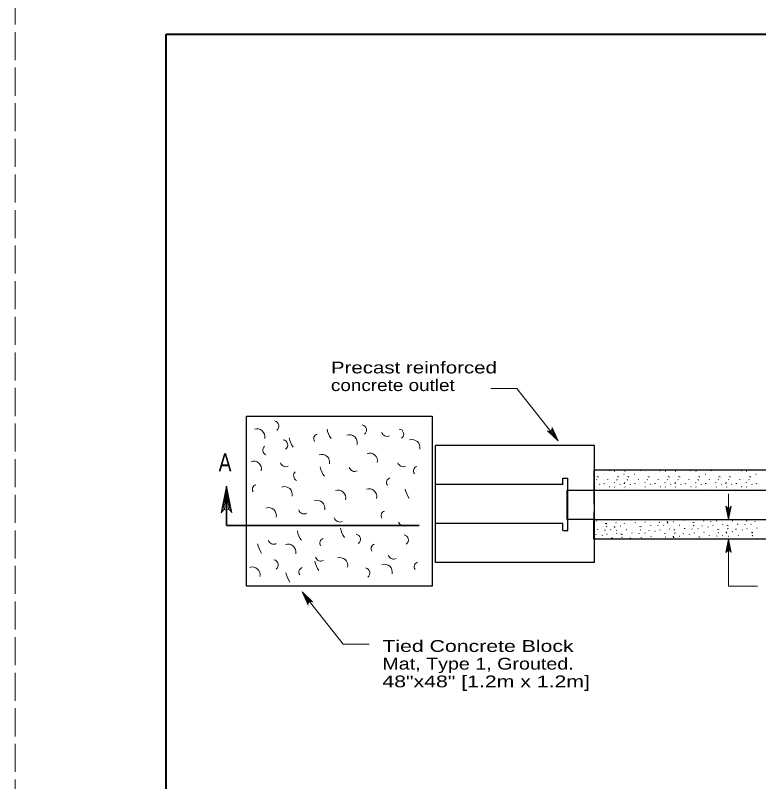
# Model space of a CAD drawing. Extents: x 1083.1 to 1117.1, y 697.4 to 741.4.
# Drawn here: x 1083.13 to 1092.98, y 708.94 to 719.1 of the extents above; entities that cross this region are included whole.
import ezdxf

# ---------------------------------------------------------------- set-up
doc = ezdxf.new("R2010")
doc.units = 0
doc.header["$LTSCALE"] = 0.062
doc.linetypes.add('LONG_DASHED', pattern=[7.5, 6, -1.5])
doc.linetypes.add('MEDIUM_DASHED', pattern=[4.5, 3, -1.5])
doc.layers.add('1', color=7, linetype='Continuous', lineweight=13)

msp = doc.modelspace()

# ---------------------------------------------------------------- linework, layer by layer
at = {"layer": '1', "lineweight": 25}
for p, q in [((1085.12642, 718.85408), (1116.62642, 718.85408)), ((1088.69717, 711.84625), (1088.69717, 713.39942)), ((1090.80558, 713.39942), (1088.69717, 713.39942)), ((1090.80558, 711.84625), (1090.80558, 713.39992)), ((1090.80308, 713.06008), (1090.80533, 713.05683)), ((1091.00475, 713.06617), (1091.007, 713.06283)), ((1091.07075, 713.06008), (1091.07308, 713.05683)), ((1091.20833, 713.06008), (1091.21058, 713.05683)), ((1091.41, 713.06617), (1091.41217, 713.06283)), ((1091.476, 713.06008), (1091.47825, 713.05683)), ((1091.67767, 713.06617), (1091.67992, 713.06283)), ((1091.74367, 713.06008), (1091.746, 713.05683)), ((1091.88117, 713.06008), (1091.8835, 713.05683)), ((1092.08292, 713.06617), (1092.08508, 713.06283)), ((1092.14892, 713.06008), (1092.15117, 713.05683)), ((1092.35058, 713.06617), (1092.35283, 713.06283)), ((1092.41658, 713.06008), (1092.41892, 713.05683)), ((1092.55408, 713.06008), (1092.55642, 713.05683)), ((1092.75583, 713.06617), (1092.758, 713.06283)), ((1092.82183, 713.06008), (1092.82408, 713.05683)), ((1090.45158, 712.27133), (1090.45158, 712.96725)), ((1090.83267, 712.947), (1090.83483, 712.94358)), ((1090.83483, 712.94575), (1090.83708, 712.94233)), ((1090.84442, 712.98292), (1090.84658, 712.988)), ((1090.8525, 712.98292), (1090.85475, 712.97967)), ((1090.92742, 713.0205), (1090.92975, 713.01708)), ((1090.98017, 712.947), (1090.98242, 712.952)), ((1091.10033, 712.947), (1091.10258, 712.94358)), ((1091.10258, 712.94575), (1091.10475, 712.94233)), ((1091.11208, 712.98292), (1091.11425, 712.988)), ((1091.12017, 712.98292), (1091.1225, 712.97967)), ((1091.19517, 713.0205), (1091.19742, 713.01708)), ((1091.23783, 712.947), (1091.24008, 712.94358)), ((1091.24008, 712.94575), (1091.24225, 712.94233)), ((1091.24958, 712.98292), (1091.25175, 712.988)), ((1091.25767, 712.98292), (1091.26, 712.97967)), ((1091.33267, 713.0205), (1091.33492, 713.01708)), ((1091.38533, 712.947), (1091.38767, 712.952)), ((1091.50558, 712.947), (1091.50775, 712.94358)), ((1091.50775, 712.94575), (1091.51, 712.94233)), ((1091.51725, 712.98292), (1091.5195, 712.988)), ((1091.52542, 712.98292), (1091.52767, 712.97967)), ((1091.60033, 713.0205), (1091.60267, 713.01708)), ((1091.65308, 712.947), (1091.65533, 712.952)), ((1091.77325, 712.947), (1091.7755, 712.94358)), ((1091.7755, 712.94575), (1091.77767, 712.94233)), ((1091.785, 712.98292), (1091.78717, 712.988)), ((1091.79308, 712.98292), (1091.79533, 712.97967)), ((1091.86808, 713.0205), (1091.87033, 713.01708)), ((1091.91075, 712.947), (1091.913, 712.94358)), ((1091.913, 712.94575), (1091.91517, 712.94233)), ((1091.9225, 712.98292), (1091.92475, 712.988)), ((1091.93058, 712.98292), (1091.93292, 712.97967)), ((1092.00558, 713.0205), (1092.00783, 713.01708)), ((1092.05825, 712.947), (1092.06058, 712.952)), ((1092.1785, 712.947), (1092.18067, 712.94358)), ((1092.18067, 712.94575), (1092.18292, 712.94233)), ((1092.19025, 712.98292), (1092.19242, 712.988)), ((1092.19833, 712.98292), (1092.20058, 712.97967)), ((1092.27325, 713.0205), (1092.27558, 713.01708)), ((1092.326, 712.947), (1092.32825, 712.952)), ((1092.44617, 712.947), (1092.44842, 712.94358)), ((1092.44842, 712.94575), (1092.45058, 712.94233)), ((1092.45792, 712.98292), (1092.46008, 712.988)), ((1092.466, 712.98292), (1092.46833, 712.97967)), ((1092.541, 713.0205), (1092.54325, 713.01708)), ((1092.58367, 712.947), (1092.58592, 712.94358)), ((1092.58592, 712.94575), (1092.58808, 712.94233)), ((1092.59542, 712.98292), (1092.59758, 712.988)), ((1092.6035, 712.98292), (1092.60583, 712.97967)), ((1092.6785, 713.0205), (1092.68075, 713.01708)), ((1092.73117, 712.947), (1092.7335, 712.952)), ((1092.85142, 712.947), (1092.85358, 712.94358)), ((1092.85358, 712.94575), (1092.85583, 712.94233)), ((1092.86308, 712.98292), (1092.86533, 712.988)), ((1092.87125, 712.98292), (1092.8735, 712.97967)), ((1092.94617, 713.0205), (1092.9485, 713.01708)), ((1090.38533, 712.88175), (1088.69717, 712.88175)), ((1090.79958, 712.9055), (1090.80192, 712.91058)), ((1090.80308, 712.85083), (1090.80533, 712.84758)), ((1090.87242, 712.88617), (1090.87458, 712.88283)), ((1090.93492, 712.89267), (1090.93708, 712.89775)), ((1091.00475, 712.85692), (1091.007, 712.85358)), ((1091.06733, 712.9055), (1091.06958, 712.91058)), ((1091.07075, 712.85083), (1091.07308, 712.84758)), ((1091.14008, 712.88617), (1091.14225, 712.88283)), ((1091.20258, 712.89267), (1091.20483, 712.89775)), ((1091.20483, 712.9055), (1091.20708, 712.91058)), ((1091.20833, 712.85083), (1091.21058, 712.84758)), ((1091.27758, 712.88617), (1091.27983, 712.88283)), ((1091.34017, 712.89267), (1091.34233, 712.89775)), ((1091.41, 712.85692), (1091.41217, 712.85358)), ((1091.4725, 712.9055), (1091.47483, 712.91058)), ((1091.476, 712.85083), (1091.47825, 712.84758)), ((1091.54533, 712.88617), (1091.5475, 712.88283)), ((1091.60783, 712.89267), (1091.61008, 712.89775)), ((1091.67767, 712.85692), (1091.67992, 712.85358)), ((1091.74025, 712.9055), (1091.7425, 712.91058)), ((1091.74367, 712.85083), (1091.746, 712.84758)), ((1091.813, 712.88617), (1091.81517, 712.88283)), ((1091.87558, 712.89267), (1091.87775, 712.89775)), ((1091.87775, 712.9055), (1091.88, 712.91058)), ((1091.88117, 712.85083), (1091.8835, 712.84758)), ((1091.9505, 712.88617), (1091.95267, 712.88283)), ((1092.01308, 712.89267), (1092.01525, 712.89775)), ((1092.08292, 712.85692), (1092.08508, 712.85358)), ((1092.14542, 712.9055), (1092.14775, 712.91058)), ((1092.14892, 712.85083), (1092.15117, 712.84758)), ((1092.21817, 712.88617), (1092.22042, 712.88283)), ((1092.28075, 712.89267), (1092.28292, 712.89775)), ((1092.35058, 712.85692), (1092.35283, 712.85358)), ((1092.41317, 712.9055), (1092.41542, 712.91058)), ((1092.41658, 712.85083), (1092.41892, 712.84758)), ((1092.48592, 712.88617), (1092.48808, 712.88283)), ((1092.54842, 712.89267), (1092.55067, 712.89775)), ((1092.55067, 712.9055), (1092.55292, 712.91058)), ((1092.55408, 712.85083), (1092.55642, 712.84758)), ((1092.62342, 712.88617), (1092.62567, 712.88283)), ((1092.686, 712.89267), (1092.68817, 712.89775)), ((1092.75583, 712.85692), (1092.758, 712.85358)), ((1092.81833, 712.9055), (1092.82067, 712.91058)), ((1092.82183, 712.85083), (1092.82408, 712.84758)), ((1092.89117, 712.88617), (1092.89333, 712.88283)), ((1092.95367, 712.89267), (1092.95583, 712.89775)), ((1090.92742, 712.81117), (1090.92975, 712.80783)), ((1091.19517, 712.81117), (1091.19742, 712.80783)), ((1091.33267, 712.81117), (1091.33492, 712.80783)), ((1091.60033, 712.81117), (1091.60267, 712.80783)), ((1091.86808, 712.81117), (1091.87033, 712.80783)), ((1092.00558, 712.81117), (1092.00783, 712.80783)), ((1092.27325, 712.81117), (1092.27558, 712.80783)), ((1092.541, 712.81117), (1092.54325, 712.80783)), ((1092.6785, 712.81117), (1092.68075, 712.80783)), ((1092.94617, 712.81117), (1092.9485, 712.80783)), ((1090.38533, 712.364), (1088.69717, 712.364)), ((1090.38533, 712.27133), (1090.38533, 712.364)), ((1090.79808, 712.41658), (1097.47717, 712.41658)), ((1090.82642, 712.39958), (1090.82967, 712.39733)), ((1090.893, 712.41658), (1090.89325, 712.4165)), ((1090.95708, 712.36258), (1090.95725, 712.36808)), ((1090.96458, 712.36567), (1090.96792, 712.36342)), ((1091.07208, 712.32558), (1091.07233, 712.33108)), ((1091.08458, 712.41408), (1091.08467, 712.41658)), ((1091.08717, 712.37642), (1091.0905, 712.37408)), ((1091.08967, 712.376), (1091.093, 712.37375)), ((1091.09292, 712.41658), (1091.09542, 712.41492)), ((1091.14675, 712.33492), (1091.15008, 712.33258)), ((1091.20233, 712.36433), (1091.2025, 712.36983)), ((1091.2805, 712.35733), (1091.28375, 712.35508)), ((1091.344, 712.3765), (1091.34733, 712.37425)), ((1091.47417, 712.38625), (1091.4775, 712.384)), ((1091.5505, 712.33792), (1091.55075, 712.34342)), ((1091.64683, 712.33208), (1091.64708, 712.33767)), ((1091.662, 712.38292), (1091.66525, 712.38067)), ((1091.6645, 712.38258), (1091.66783, 712.38025)), ((1091.72158, 712.34142), (1091.72492, 712.33917)), ((1091.77433, 712.38367), (1091.77458, 712.38917)), ((1091.77717, 712.37092), (1091.77725, 712.37642)), ((1091.79808, 712.33425), (1091.80142, 712.332)), ((1091.84908, 712.39292), (1091.85242, 712.39067)), ((1091.92825, 712.34408), (1091.93158, 712.34175)), ((1091.98283, 712.41542), (1091.98608, 712.41317)), ((1092.1135, 712.37842), (1092.11367, 712.38392)), ((1092.11608, 712.34075), (1092.11942, 712.33842)), ((1092.11858, 712.34033), (1092.12192, 712.33808)), ((1092.121, 712.3815), (1092.12433, 712.37925)), ((1092.23125, 712.32867), (1092.23142, 712.33417)), ((1092.25283, 712.396), (1092.25308, 712.4015)), ((1092.34917, 712.39017), (1092.34942, 712.39567)), ((1092.37283, 712.34075), (1092.37625, 712.33858)), ((1092.42392, 712.3995), (1092.42717, 712.39717)), ((1092.50033, 712.39233), (1092.50375, 712.39008)), ((1092.503, 712.35058), (1092.50642, 712.34833)), ((1092.56758, 712.33625), (1092.56775, 712.34167)), ((1092.57508, 712.33925), (1092.57842, 712.33708)), ((1092.6305, 712.40217), (1092.63392, 712.39983)), ((1092.70692, 712.35375), (1092.70717, 712.35925)), ((1092.80325, 712.34792), (1092.8035, 712.3535)), ((1092.81842, 712.39875), (1092.82167, 712.3965)), ((1092.82092, 712.39842), (1092.82417, 712.39608)), ((1092.878, 712.35725), (1092.88133, 712.35492)), ((1092.9335, 712.38675), (1092.93367, 712.39225)), ((1090.38533, 712.27133), (1090.45158, 712.27133)), ((1090.84825, 712.27983), (1090.84842, 712.28533)), ((1090.94458, 712.27408), (1090.94475, 712.27958)), ((1090.95967, 712.32483), (1090.963, 712.32258)), ((1090.96217, 712.3245), (1090.9655, 712.32225)), ((1091.01925, 712.28333), (1091.02258, 712.28108)), ((1091.07483, 712.31283), (1091.075, 712.31833)), ((1091.09575, 712.27617), (1091.09908, 712.274)), ((1091.09842, 712.2345), (1091.10183, 712.23225)), ((1091.22592, 712.286), (1091.22933, 712.28375)), ((1091.30233, 712.23758), (1091.30258, 712.24317)), ((1091.39867, 712.23183), (1091.39892, 712.23733)), ((1091.41117, 712.32033), (1091.41133, 712.32583)), ((1091.41375, 712.28267), (1091.41708, 712.28033)), ((1091.41625, 712.28233), (1091.41958, 712.28)), ((1091.41867, 712.32342), (1091.422, 712.32117)), ((1091.47342, 712.24117), (1091.47667, 712.23883)), ((1091.52892, 712.27058), (1091.52908, 712.27608)), ((1091.60708, 712.26358), (1091.61042, 712.26133)), ((1091.67058, 712.28275), (1091.67392, 712.2805)), ((1091.73775, 712.22667), (1091.73792, 712.23217)), ((1091.74525, 712.22967), (1091.74867, 712.2275)), ((1091.80075, 712.29258), (1091.80408, 712.29025)), ((1091.86525, 712.27817), (1091.86542, 712.28367)), ((1091.86783, 712.24042), (1091.87117, 712.23808)), ((1091.87033, 712.24008), (1091.87367, 712.23775)), ((1091.87275, 712.28117), (1091.87617, 712.279)), ((1091.983, 712.22842), (1091.98317, 712.23392)), ((1092.00458, 712.29567), (1092.00483, 712.30117)), ((1092.101, 712.28992), (1092.10117, 712.29542)), ((1092.12467, 712.2405), (1092.128, 712.23825)), ((1092.17567, 712.29925), (1092.179, 712.29692)), ((1092.25483, 712.25033), (1092.25825, 712.24808)), ((1092.30942, 712.32167), (1092.31267, 712.31942)), ((1092.44008, 712.28467), (1092.44025, 712.29017)), ((1092.44267, 712.247), (1092.446, 712.24467)), ((1092.44517, 712.24667), (1092.4485, 712.24433)), ((1092.44758, 712.28775), (1092.45092, 712.2855)), ((1092.55508, 712.24767), (1092.55525, 712.25317)), ((1092.55783, 712.235), (1092.558, 712.24042)), ((1092.57017, 712.2985), (1092.5735, 712.29617)), ((1092.57267, 712.29817), (1092.576, 712.29583)), ((1092.62975, 712.257), (1092.63308, 712.25467)), ((1092.68533, 712.2865), (1092.6855, 712.292)), ((1092.7635, 712.2795), (1092.76675, 712.27725)), ((1092.827, 712.29858), (1092.83033, 712.29633)), ((1092.89417, 712.2425), (1092.89433, 712.248)), ((1092.90167, 712.2455), (1092.905, 712.24333)), ((1092.95708, 712.30842), (1092.9605, 712.30608)), ((1097.47717, 712.15767), (1090.81242, 712.15767)), ((1090.82658, 712.21258), (1090.82675, 712.21808)), ((1090.90483, 712.20558), (1090.90808, 712.20333)), ((1090.96825, 712.22467), (1090.97158, 712.22242)), ((1091.03542, 712.16858), (1091.03558, 712.17408)), ((1091.043, 712.17158), (1091.04633, 712.16942)), ((1091.16292, 712.22008), (1091.16308, 712.22558)), ((1091.16558, 712.18233), (1091.16883, 712.18008)), ((1091.16808, 712.182), (1091.17142, 712.17975)), ((1091.1705, 712.22317), (1091.17383, 712.22092)), ((1091.28075, 712.17033), (1091.28083, 712.17583)), ((1091.35892, 712.16333), (1091.36217, 712.16108)), ((1091.42233, 712.18242), (1091.42567, 712.18025)), ((1091.5525, 712.19225), (1091.55592, 712.19)), ((1091.74033, 712.18892), (1091.74367, 712.18658)), ((1091.74292, 712.18858), (1091.74617, 712.18625)), ((1091.85275, 712.18958), (1091.853, 712.19517)), ((1091.8555, 712.17692), (1091.85567, 712.18242)), ((1091.9275, 712.19892), (1091.93075, 712.19658)), ((1092.06117, 712.22142), (1092.0645, 712.21917)), ((1092.19183, 712.18442), (1092.192, 712.18992)), ((1092.19933, 712.18742), (1092.20275, 712.18525)), ((1092.33125, 712.20192), (1092.33142, 712.2075)), ((1092.42758, 712.19617), (1092.42775, 712.20167)), ((1092.50225, 712.2055), (1092.50558, 712.20317)), ((1092.57875, 712.19825), (1092.58208, 712.19608)), ((1092.70892, 712.20808), (1092.71233, 712.20583)), ((1092.78533, 712.15975), (1092.7855, 712.16525)), ((1092.88183, 712.15767), (1092.88192, 712.1595)), ((1092.89675, 712.20475), (1092.90008, 712.20242)), ((1092.89925, 712.20442), (1092.90258, 712.20208)), ((1092.95642, 712.16325), (1092.95967, 712.16092)), ((1090.80558, 711.84625), (1088.69717, 711.84625))]:
    msp.add_line(p, q, dxfattribs=at)
at = {"layer": '1'}
for p, q in [((1090.20283, 713.58675), (1090.32167, 713.46158)), ((1090.21583, 713.58892), (1090.32167, 713.46158)), ((1090.22667, 713.5945), (1090.32167, 713.46158)), ((1090.23742, 713.60592), (1090.32167, 713.46158)), ((1090.24267, 713.61767), (1090.32167, 713.46158)), ((1085.87833, 712.53533), (1085.92792, 712.85967)), ((1085.89908, 712.54767), (1085.92792, 712.85967)), ((1085.92792, 712.55333), (1085.92792, 712.85967)), ((1085.95058, 712.55), (1085.92792, 712.85967)), ((1085.97275, 712.53917), (1085.92792, 712.85967)), ((1092.58383, 712.757), (1092.58383, 712.41658)), ((1092.56133, 712.57683), (1092.58383, 712.41658)), ((1092.5725, 712.57142), (1092.58383, 712.41658)), ((1092.60858, 712.57875), (1092.58383, 712.41658)), ((1092.59817, 712.57258), (1092.58383, 712.41658)), ((1092.58383, 712.56975), (1092.58383, 712.41658)), ((1092.559, 711.99558), (1092.58383, 712.15767)), ((1092.56942, 712.00167), (1092.58383, 712.15767)), ((1092.58383, 712.0045), (1092.58383, 712.15767)), ((1092.59508, 712.00292), (1092.58383, 712.15767)), ((1092.60625, 711.99742), (1092.58383, 712.15767)), ((1087.02283, 711.32475), (1086.92783, 711.45767)), ((1087.01208, 711.31333), (1086.92783, 711.45767)), ((1087.00683, 711.30158), (1086.92783, 711.45767)), ((1087.03367, 711.33033), (1086.92783, 711.45767)), ((1087.04667, 711.3325), (1086.92783, 711.45767))]:
    msp.add_line(p, q, dxfattribs=at)
at = {"layer": '1', "lineweight": 35}
for p, q in [((1085.92792, 712.34042), (1085.92792, 712.85967)), ((1088.47858, 712.33808), (1085.92792, 712.34042)), ((1090.81242, 712.15767), (1090.79808, 712.15767))]:
    msp.add_line(p, q, dxfattribs=at)
at = {"layer": '1', "linetype": 'MEDIUM_DASHED', "lineweight": 25}
msp.add_line((1090.79808, 712.80517), (1090.79808, 712.41658), dxfattribs=at)
at = {"layer": '1', "linetype": 'LONG_DASHED'}
msp.add_lwpolyline([(1083.12642, 697.35408), (1117.12642, 697.35408), (1117.12642, 719.35408), (1083.12642, 719.35408)], close=True, dxfattribs=at)
at = {"layer": '1', "lineweight": 25}
for points in [[(1116.62642, 697.85408), (1085.12642, 697.85408), (1085.12642, 718.85408)], [(1097.47983, 713.07375), (1090.79808, 713.07375), (1090.79808, 712.80517), (1097.47983, 712.80517)], [(1090.38533, 712.88175), (1090.38533, 712.96725), (1090.45158, 712.96725)], [(1090.79808, 712.15767), (1090.79808, 712.41658), (1090.44167, 712.41658), (1090.44167, 712.80517), (1090.79808, 712.80517)]]:
    msp.add_lwpolyline(points, dxfattribs=at)
at = {"layer": '1', "lineweight": 40}
msp.add_lwpolyline([(1085.12642, 718.85408), (1116.62642, 718.85408), (1116.62642, 697.85408), (1085.12642, 697.85408)], close=True, dxfattribs=at)
msp.add_lwpolyline([(1085.12642, 718.85408), (1116.62642, 718.85408), (1116.62642, 697.85408), (1085.12642, 697.85408)], close=True, dxfattribs=at)
at = {"layer": '1'}
for points in [[(1090.30592, 713.48358), (1089.77683, 714.155), (1089.43075, 714.155)], [(1090.24267, 713.63717), (1090.32167, 713.46158), (1090.18125, 713.59325)], [(1085.85708, 712.50567), (1085.92792, 712.85967), (1085.99875, 712.50567)], [(1092.61917, 712.59358), (1092.58383, 712.41658), (1092.54842, 712.59358)], [(1092.54842, 711.98067), (1092.58383, 712.15767), (1092.61917, 711.98067)], [(1092.58383, 712.15767), (1092.58383, 711.53325), (1092.9645, 711.53325), (1092.9645, 711.53325)], [(1087.00683, 711.28208), (1086.92783, 711.45767), (1087.06825, 711.326)], [(1086.94358, 711.43567), (1087.47267, 710.76425), (1087.81875, 710.76425)]]:
    msp.add_lwpolyline(points, dxfattribs=at)
at = {"layer": '1', "lineweight": 25}
msp.add_lwpolyline([(1088.65192, 711.53392), (1086.19292, 711.53392), (1086.19292, 713.78875), (1088.65192, 713.78875)], close=True, dxfattribs=at)
at = {"layer": '1'}
for centre, radius, start, end in [((1086.55458, 713.65842), 0.06689, 303.67027, 82.84336), ((1087.71688, 713.60474), 0.06689, 303.67027, 82.84336), ((1086.33037, 713.51718), 0.10462, 347.15932, 108.38347), ((1087.14561, 713.48956), 0.06313, 107.11941, 214.34733), ((1087.52364, 713.6588), 0.26761, 188.97541, 218.01059), ((1088.05335, 713.59238), 0.072, 194.8887, 297.82099), ((1088.20854, 713.55108), 0.06689, 303.67027, 82.84336), ((1090.203, 713.62766), 0.04075, 237.62129, 13.44741), ((1086.67058, 713.40792), 0.06689, 303.67027, 82.84336), ((1087.023, 713.5425), 0.26761, 188.97541, 218.01059), ((1087.5552, 713.43668), 0.10462, 347.15932, 108.38347), ((1088.3867, 713.3741), 0.10462, 347.15932, 108.38347), ((1086.48042, 713.33842), 0.07212, 135, 242.45942), ((1087.1887, 713.17735), 0.10462, 347.15932, 108.38347), ((1087.82345, 713.19527), 0.10462, 347.15932, 108.38347), ((1086.28567, 713.08792), 0.10462, 347.15932, 108.38347), ((1086.71225, 713.18992), 0.072, 194.8887, 297.82099), ((1088.26794, 713.18988), 0.072, 194.8887, 297.82099), ((1086.8885, 712.99983), 0.07212, 135, 242.45942), ((1087.4343, 713.15797), 0.26761, 188.97541, 218.01059), ((1087.62419, 713.12729), 0.072, 194.8887, 297.82099), ((1088.46877, 713.06031), 0.06313, 107.11941, 214.34733), ((1088.11119, 712.90823), 0.06313, 107.11941, 214.34733), ((1086.332, 712.81883), 0.06313, 107.11941, 214.34733), ((1086.69375, 712.74933), 0.10462, 347.15932, 108.38347), ((1087.4032, 712.70335), 0.10462, 347.15932, 108.38347), ((1087.81453, 712.72127), 0.10462, 347.15932, 108.38347), ((1088.5608, 712.8628), 0.26761, 188.97541, 218.01059), ((1087.12612, 712.56918), 0.10462, 347.15932, 108.38347), ((1085.92799, 712.47705), 0.0764, 22.08782, 157.91395), ((1086.48237, 712.47085), 0.10462, 347.15932, 108.38347), ((1086.95369, 712.56388), 0.072, 194.8887, 297.82099), ((1092.58375, 712.60788), 0.0382, 202.08782, 337.91395), ((1087.42752, 712.45654), 0.072, 194.8887, 297.82099), ((1088.03961, 712.47006), 0.06313, 107.11941, 214.34733), ((1088.27685, 712.40288), 0.072, 194.8887, 297.82099), ((1087.1303, 712.3083), 0.26761, 188.97541, 218.01059), ((1087.70247, 712.34413), 0.26761, 188.97541, 218.01059), ((1086.55135, 712.16146), 0.072, 194.8887, 297.82099), ((1087.22602, 712.10339), 0.06313, 107.11941, 214.34733), ((1087.63638, 712.15591), 0.06689, 303.67027, 82.84336), ((1088.27113, 712.14699), 0.06689, 303.67027, 82.84336), ((1086.6028, 712.13838), 0.26761, 188.97541, 218.01059), ((1086.74162, 711.98793), 0.10462, 347.15932, 108.38347), ((1087.90552, 712.03181), 0.06313, 107.11941, 214.34733), ((1088.14277, 711.96471), 0.072, 194.8887, 297.82099), ((1092.58383, 711.9664), 0.0382, 22.08782, 157.91395), ((1086.54563, 711.81608), 0.06689, 303.67027, 82.84336), ((1087.36272, 711.90588), 0.26761, 188.97541, 218.01059), ((1087.17719, 711.93788), 0.072, 194.8887, 297.82099), ((1087.43003, 711.80902), 0.10462, 347.15932, 108.38347), ((1088.02012, 711.7196), 0.10462, 347.15932, 108.38347), ((1088.47777, 711.79039), 0.06313, 107.11941, 214.34733), ((1086.26778, 711.68385), 0.10462, 347.15932, 108.38347), ((1086.94894, 711.71881), 0.06313, 107.11941, 214.34733), ((1087.76154, 711.70874), 0.06689, 303.67027, 82.84336), ((1086.9783, 711.7538), 0.26761, 188.97541, 218.01059), ((1087.04649, 711.29161), 0.04075, 57.62129, 193.44741)]:
    msp.add_arc(centre, radius, start, end, dxfattribs=at)

# ---------------------------------------------------------------- texts
for s, height, width, p in [('Precast reinforced', 0.156, 1.3, (1087.31067, 714.35525)), ('concrete outlet', 0.156, 1.2, (1087.31067, 714.12125)), ('A', 0.24, 0.8, (1085.82158, 713.05475)), ('Tied Concrete Block ', 0.156, 1.35, (1087.99283, 710.662)), ('Mat, Type 1, Grouted.', 0.156, 1.25, (1087.99283, 710.42733)), ('48"x48" [1.2m x 1.2m] ', 0.156, 1.35, (1087.99283, 710.19267))]:
    msp.add_text(s, height=height, dxfattribs=dict(at, width=width)).set_placement(p)

doc.saveas('drawing.dxf')
